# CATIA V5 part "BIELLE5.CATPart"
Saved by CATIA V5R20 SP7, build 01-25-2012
Part number: bielle5
Publications: "droite_bielle_5", "droite_pivot_5_4", "droite_pivot_5_6_7"
Bounding box of the stored display mesh (mm): x -0.5 to 0, y 1.52 to 2.08, z 1.17 to 1.4
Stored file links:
  U:\IAO\BIELLE5.CATPart
  U:\IAO\skl_brevet_iao.CATProduct
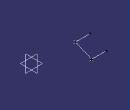
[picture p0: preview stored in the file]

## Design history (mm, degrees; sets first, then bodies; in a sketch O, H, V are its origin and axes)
Set1
  Point1 "point F": linked copy from another document
  Point2 "point G": linked copy from another document
Set2
  Line1 "droite_bielle_5": type PtPt, FirstPoint Point1, SecondPoint Point2
  Line2 "droite_pivot_5_4": type Normal, RefPoint Point1, RefSkin yz-plane, Start 0, End 0.5
  Line3 "droite_pivot_5_6_7": type Normal, RefPoint Point2, RefSkin yz-plane, Start 0, End 0.5
Body1 (main body)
